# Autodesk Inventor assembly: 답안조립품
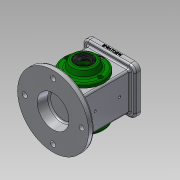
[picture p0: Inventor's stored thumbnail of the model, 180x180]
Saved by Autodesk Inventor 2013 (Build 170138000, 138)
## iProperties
Created: 2018-10
Part Number: 답안조립품
Document SubType Name: Assembly
Designer: hana-cad17
Author: hana-cad17
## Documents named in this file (6)
- C:\Documents and Settings\hana-cad17\바탕 화면\481007V1042\답안조립품.iam
- C:\Documents and Settings\hana-cad17\바탕 화면\481007V1042\본체.ipt
- C:\Documents and Settings\hana-cad17\바탕 화면\481007V1042\앞커버.ipt
- C:\Documents and Settings\hana-cad17\바탕 화면\481007V1042\뒤커버.ipt
- C:\Documents and Settings\hana-cad17\바탕 화면\481007V1042\오일 실 17 30 8.ipt
- C:\Documents and Settings\hana-cad17\바탕 화면\481007V1042\볼트 M4 x 8.ipt
